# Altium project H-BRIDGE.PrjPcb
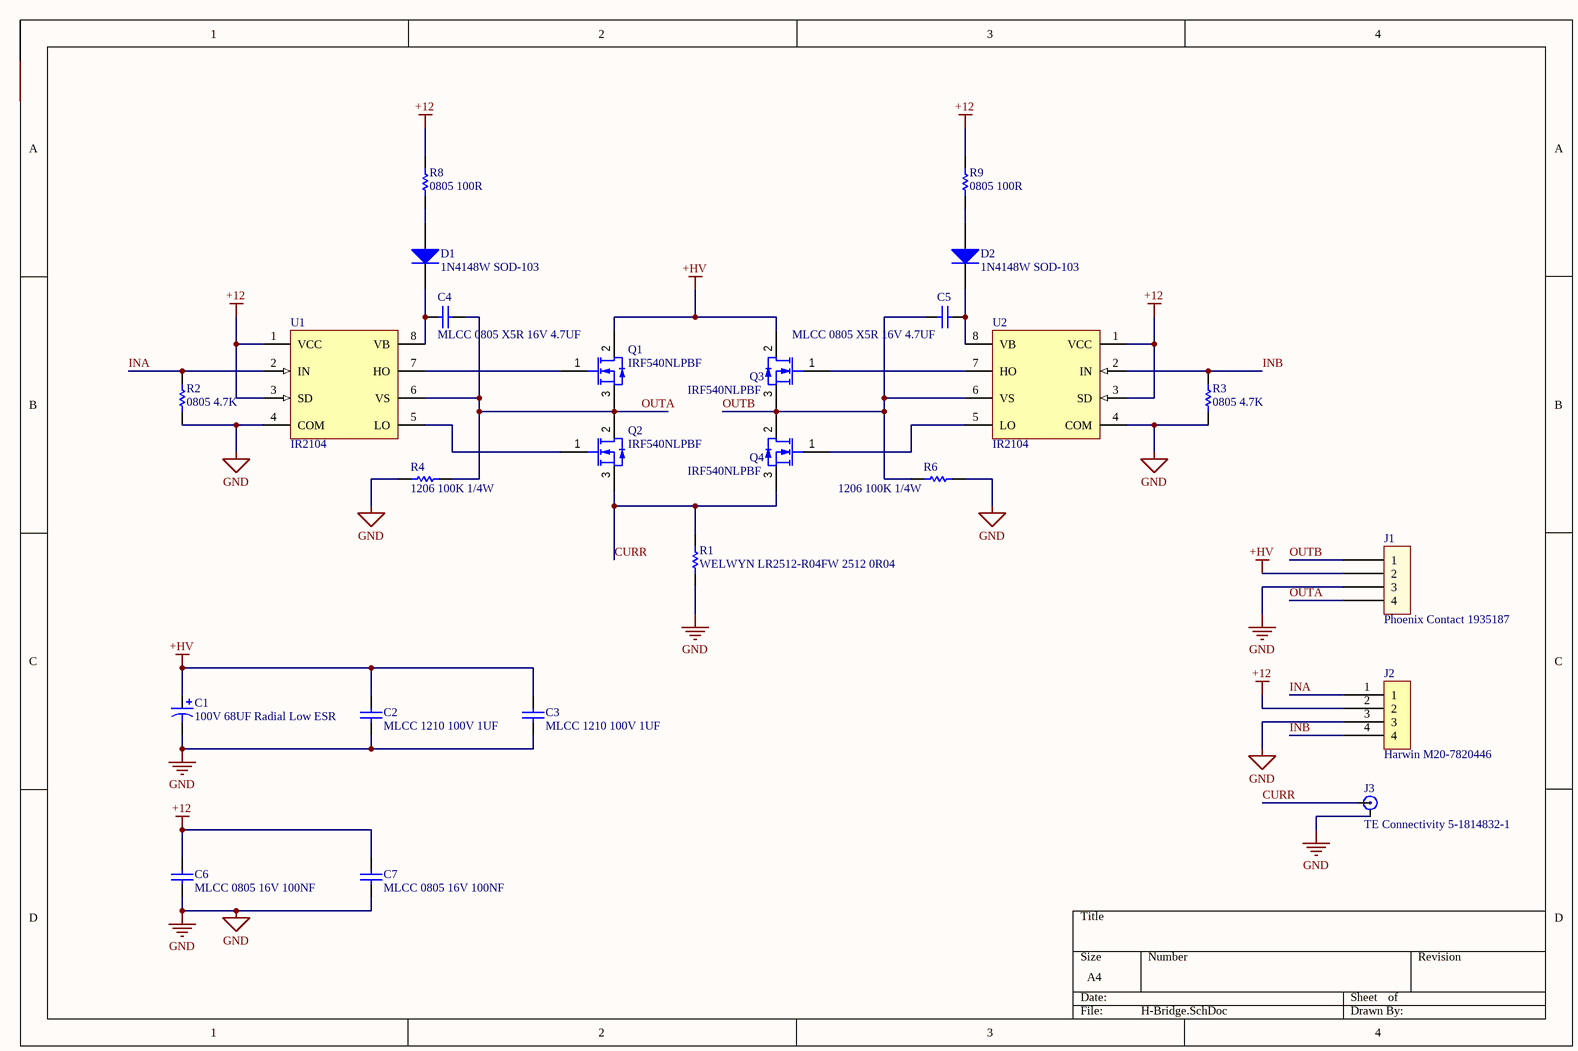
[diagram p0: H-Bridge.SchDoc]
1 sheet, 25 parts. Net scope: global (net labels, ports and power ports of the same name join across sheets).

## Sheet H-Bridge.SchDoc
size A4

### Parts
C1  100V 68UF Radial Low ESR  [PCB-1n77byy44zdxw4e2p3wb-1]
C2  MLCC 1210 100V 1UF  [CAPC3225X279X50NL20T25]
C3  MLCC 1210 100V 1UF  [CAPC3225X279X50NL20T25]
C4  MLCC 0805 X5R 16V 4.7UF  [CAPC2013X95X45NL10T25]
C5  MLCC 0805 X5R 16V 4.7UF  [CAPC2013X95X45NL10T25]
C6  MLCC 0805 16V 100NF  [CAPC2013X94X50ML20T25]
C7  MLCC 0805 16V 100NF  [CAPC2013X94X50ML20T25]
D1  1N4148W SOD-103  [PCB-726b3olvcjf0u3zwqet5-1]
D2  1N4148W SOD-103  [PCB-726b3olvcjf0u3zwqet5-1]
J1  Phoenix Contact 1935187  [PCB-ze6c03jjo3jausbqidy3-1]
J2  Harwin M20-7820446  [PCB-tt6oa92k1i3euqam155k-1]
J3  TE Connectivity 5-1814832-1  [PCB-TE Connectivity 5-1814832-1]
Q1  IRF540NLPBF  [PCB-9181541-2]
Q2  IRF540NLPBF  [PCB-9181541-2]
Q3  IRF540NLPBF  [PCB-9181541-2]
Q4  IRF540NLPBF  [PCB-9181541-2]
R1  WELWYN LR2512-R04FW 2512 0R04  [PCB-ngebvzhdids6xwxblt59-1]
R2  0805 4.7K  [RESC2013X50X30LL20T20]
R3  0805 4.7K  [RESC2013X50X30LL20T20]
R4  1206 100K 1/4W  [RESC3216X60X45NL10T20]
R6  1206 100K 1/4W  [RESC3216X60X45NL10T20]
R8  0805 100R  [RESC2013X70X40LL20T20]
R9  0805 100R  [RESC2013X70X40LL20T20]
U1  IR2104  [PCB-1161383-2]
U2  IR2104  [PCB-1161383-2]

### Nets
+12: C6.2 C7.2 J2.2 R8.2 R9.2 U1.1(VCC) U1.3(SD) U2.1(VCC) U2.3(SD)
+HV: C1.1 C2.2 C3.2 J1.2 Q1.2(D) Q3.2(D)
GND: C1.2 C2.1 C3.1 C6.1 C7.1 J1.3 J2.3 J3.2 R1.1 R2.1 R3.1 R4.2 R6.1 U1.4(COM) U2.4(COM)
CURR: J3.1 Q2.3(S) Q4.3(S) R1.2
INA: J2.1 R2.2 U1.2(IN)
INB: J2.4 R3.2 U2.2(IN)
OUTA: C4.1 J1.4 Q1.3(S) Q2.2(D) R4.1 U1.6(VS)
OUTB: C5.2 J1.1 Q3.3(S) Q4.2(D) R6.2 U2.6(VS)
NetC4_2: C4.2 D1.2(K) U1.8(VB)
NetC5_1: C5.1 D2.2(K) U2.8(VB)
NetD1_1: D1.1(A) R8.1
NetD2_1: D2.1(A) R9.1
NetQ1_1: Q1.1(G) U1.7(HO)
NetQ2_1: Q2.1(G) U1.5(LO)
NetQ3_1: Q3.1(G) U2.7(HO)
NetQ4_1: Q4.1(G) U2.5(LO)

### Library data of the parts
C1 = UHE2A680MPD: HE Series 68 uF 100 V 105°C Ø10 x 16 mm LS=5 mm Radial Aluminum Electrolytic Cap; Equivalent Series Resistance (ESR): 1.50 Ω; Capacitance: 68.0 µF; Lead-Free Status: Lead Free; Capacitance Tolerance: ±20%
C2 C3 = 12101C105KAT2A: CAP CER 1UF 100V 10% X7R 1210; Voltage Rating (DC): 100.0 V; Dielectric Material: Ceramic Multilayer; Capacitance: 1e-06 F; Lead-Free Status: Lead Free
C4 C5 = GRM219R61C475KE15D: Multilayer Ceramic Capacitors MLCC - SMD/SMT 4.7uF 16Volts 10%; Capacitance: 4.7e-06 F; Case/Package (SI): 2012; Lead-Free Status: Lead Free; Voltage Rating (DC): 16.0 V
C6 C7 = 0805YC104KAT2A: CAP CER 0.1UF 16V 10% X7R 0805; Capacitance: 1e-07 F; Case/Package (SI): 2012; Lead-Free Status: Lead Free; Voltage Rating (DC): 16.0 V
D1 D2 = 1N4148W-TP: 1N4148W Series 100 V 150 mA 4 ns SMT High Speed Switching Diode - SOD-123; Current Rating: 150 mA; Output Current: 150 mA (max); Voltage Rating (DC): 100 V; Polarity: Standard; Capacitance: 4.00 pF; Lead-Free Status: Lead Free
J1 = 1935187: Conn; Term Blk; PCB; Screw; 4; 5 mm; Front; 26-14 AWG; 17.5 A; 250 V; Solder; Pin Pitch: 5.00 mm; Lead-Free Status: Lead Free; Number of Positions: 4; Voltage Rating (DC): 508 mV
J2 = CMP-2481958-4: Conn Socket Strip SKT 4 POS 2.54mm Solder ST Thru-Hole Tube; Contact Resistance: 15.0 mΩ; Insulation Resistance: 1.00 MΩ; Gender: Female; Number of Mating Cycles: 50; Current Rating: 3.00 A; Number of Contacts: 4
J3 = 5-1814832-1: SMA 50 O Female Straight PCB Socket Threaded RF Jack Connector; Number of Mating Cycles: 50; ELV Compliant: Compliant; Insulation Resistance: 5000000000.0 Ω; Gender: Male; Lead-Free Status: Lead Free; Dielectric Material: Teflon
Q1-Q4 = CMP-9181541-13: Trans MOSFET N-CH 100V 33A 3-Pin(3+Tab) TO-220AB; Drain to Source Voltage (Vds): 100.0 V; Continuous Drain Current (Ids): 33.0 A; Rise Time: 3.5e-08 s; Current Rating: 27.0 A; Lead-Free Status: Contains Lead
R1 = WSL2512R0400FEA: WSL Series 2512 1 W 0.04 Ohm ±1% ±75 ppm/°C SMT Power Metal Strip® Resistor; Resistance: 40.0 mΩ; Lead-Free Status: Lead Free; Voltage Rating (DC): 200 mV; Power Rating: 1.00 W; Case/Package (SI): 2512
R2 R3 = CRCW08054K70JNEA: Res Thick Film 0805 4.7K Ohm 5% 0.125W(1/8W) ±200ppm/C Molded SMD Paper T/R; Case/Package (SI): 2012; Lead-Free Status: Lead Free; Resistance: 4700.0 Ω; Temperature Coefficient: 200.0 ppm/°C; Voltage Rating (DC): 150.0 V
R4 R6 = CRCW1206100KJNEA: RES SMD 100K OHM 5% 1/4W 1206; Case/Package (SI): 3216; Lead-Free Status: Lead Free; Power Rating: 0.25 W; Resistance: 100000.0 Ω; Temperature Coefficient: 200.0 ppm/°C; Voltage Rating (DC): 200.0 V
R8 R9 = ERJ-6GEYJ101V: Thick Film Resistors - SMD 0805 100ohms 5% Tol; Case/Package (SI): 2012; Lead-Free Status: Lead Free; Power Rating: 0.125 W; Resistance: 100.0 Ω; Voltage Rating (DC): 150.0 V
U1 U2 = IR2104: INTERNATIONAL RECTIFIER   IR2104   IC, DRIVER, MOSFET, 2104, DIP8; Lead-Free Status: Contains Lead; Number of Outputs: 2; Output Current: 0.21 A; Output Voltage: 620.0 V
